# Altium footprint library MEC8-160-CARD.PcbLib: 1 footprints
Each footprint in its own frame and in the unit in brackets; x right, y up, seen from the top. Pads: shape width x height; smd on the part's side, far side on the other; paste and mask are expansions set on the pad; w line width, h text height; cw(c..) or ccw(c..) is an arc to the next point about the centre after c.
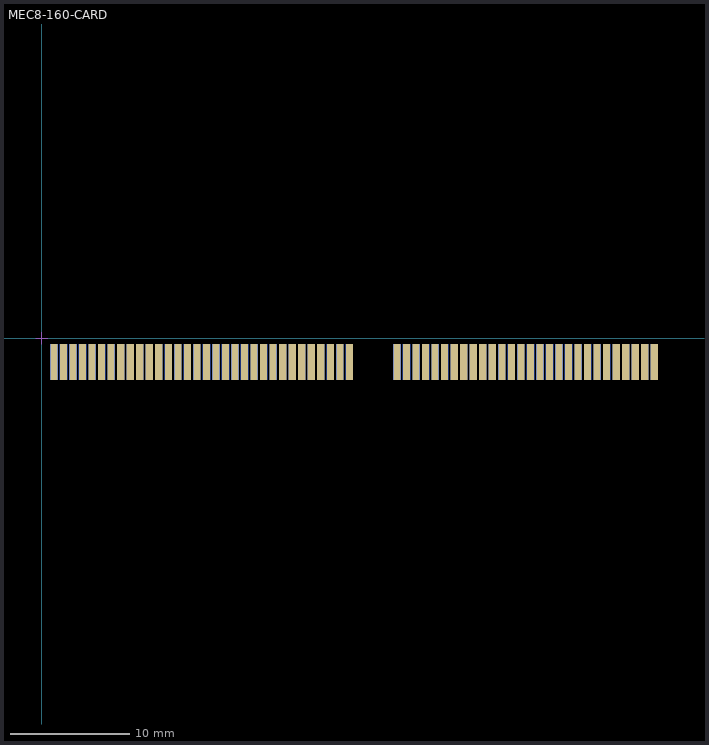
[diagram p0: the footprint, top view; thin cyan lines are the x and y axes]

## MEC8-160-CARD [mm] "edge card; inserts into MEC8-160 connector"
height 8.65
pads (120):
  rect 0.6x3 smd far side: 1(1.025,-2) 3(1.825,-2) 5(2.625,-2) 7(3.425,-2) 9(4.225,-2) 11(5.025,-2) 13(5.825,-2) 15(6.625,-2) 17(7.425,-2) 19(8.225,-2) 21(9.025,-2) 23(9.825,-2) 25(10.625,-2) 27(11.425,-2) 29(12.225,-2) 31(13.025,-2) 33(13.825,-2) 35(14.625,-2) 37(15.425,-2) 39(16.225,-2) 41(17.025,-2) 43(17.825,-2) 45(18.625,-2) 47(19.425,-2) 49(20.225,-2) 51(21.025,-2) 53(21.825,-2) 55(22.625,-2) 57(23.425,-2) 59(24.225,-2) 61(25.025,-2) 63(25.825,-2) 65(29.825,-2) 67(30.625,-2) 69(31.425,-2) 71(32.225,-2) 73(33.025,-2) 75(33.825,-2) 77(34.625,-2) 79(35.425,-2) 81(36.225,-2) 83(37.025,-2) 85(37.825,-2) 87(38.625,-2) 89(39.425,-2) 91(40.225,-2) 93(41.025,-2) 95(41.825,-2) 97(42.625,-2) 99(43.425,-2) 101(44.225,-2) 103(45.025,-2) 105(45.825,-2) 107(46.625,-2) 109(47.425,-2) 111(48.225,-2) 113(49.025,-2) 115(49.825,-2) 117(50.625,-2) 119(51.425,-2)
  rect 0.6x3 smd: 2(1.025,-2) 4(1.825,-2) 6(2.625,-2) 8(3.425,-2) 10(4.225,-2) 12(5.025,-2) 14(5.825,-2) 16(6.625,-2) 18(7.425,-2) 20(8.225,-2) 22(9.025,-2) 24(9.825,-2) 26(10.625,-2) 28(11.425,-2) 30(12.225,-2) 32(13.025,-2) 34(13.825,-2) 36(14.625,-2) 38(15.425,-2) 40(16.225,-2) 42(17.025,-2) 44(17.825,-2) 46(18.625,-2) 48(19.425,-2) 50(20.225,-2) 52(21.025,-2) 54(21.825,-2) 56(22.625,-2) 58(23.425,-2) 60(24.225,-2) 62(25.025,-2) 64(25.825,-2) 66(29.825,-2) 68(30.625,-2) 70(31.425,-2) 72(32.225,-2) 74(33.025,-2) 76(33.825,-2) 78(34.625,-2) 80(35.425,-2) 82(36.225,-2) 84(37.025,-2) 86(37.825,-2) 88(38.625,-2) 90(39.425,-2) 92(40.225,-2) 94(41.025,-2) 96(41.825,-2) 98(42.625,-2) 100(43.425,-2) 102(44.225,-2) 104(45.025,-2) 106(45.825,-2) 108(46.625,-2) 110(47.425,-2) 112(48.225,-2) 114(49.025,-2) 116(49.825,-2) 118(50.625,-2) 120(51.425,-2)
Top Solder:
  region: -0.1,0.1 26.7,0.1 26.7,-3.6 -0.1,-3.6
  region: 28.9,-3.6 52.6,-3.6 52.6,0.1 28.9,0.1
Bottom Solder:
  region: 52.6,0.1 28.9,0.1 28.9,-3.6 52.6,-3.6
  region: 26.7,-3.6 -0.1,-3.6 -0.1,0.1 26.7,0.1
Mechanical 13:
  text ".Designator" at 0.254,0.254 h1.52
Mechanical 15:
  lines w0.05: -0.5,0 0.5,0 ; 0,-0.5 0,0.5
Drill Drawing:
  lines w0.01: 0,-4 0,0 26.625,0 26.625,-5.3 ccw(c27.825,-5.3) 29.025,-5.3 29.025,0 52.45,0 52.45,-4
